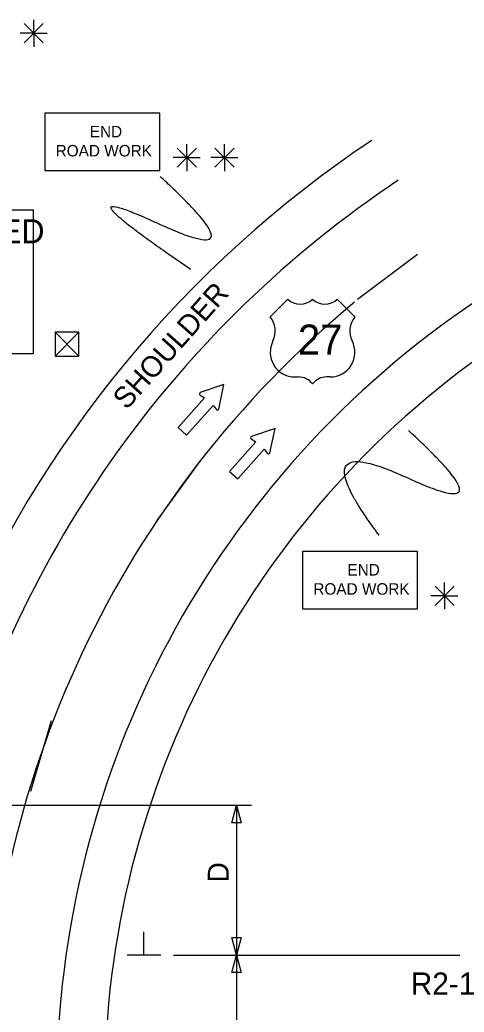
# Model space of a CAD drawing. Extents: x 16556 to 18479, y 5704 to 6974.
# Drawn here: x 17029.3 to 17177.7, y 6550.3 to 6881.5 of the extents above; entities that cross this region are included whole.
import ezdxf

# ---------------------------------------------------------------- set-up
doc = ezdxf.new("R2010")
doc.units = 0
for name, color, linetype in [('ALI_LEGAL_EX', 7, 'Continuous'), ('MT_SCRATCH_LEVEL_E', 7, 'Continuous'), ('PAVT_EDGE_EX', 7, 'Continuous'), ('TRAFFIC_SIGNS_PR', 7, 'Continuous'), ('TYPICAL_EX', 7, 'Continuous'), ('TYPICAL_TEXT_DIMEN_PR', 7, 'Continuous')]:
    doc.layers.add(name, color=color, linetype=linetype)

msp = doc.modelspace()

# ---------------------------------------------------------------- linework, layer by layer
at = {"layer": 'ALI_LEGAL_EX'}
msp.add_line((17039.84, 6647.53), (17032.85, 6623.88), dxfattribs=at)
for points in [[(17142.04, 6788.34), (17162.08, 6803.27)], [(17075.14, 6714.42), (17089.89, 6734.61)]]:
    msp.add_lwpolyline(points, dxfattribs=at)
msp.add_arc((17357.65, 6525.15), 340, 129.5666, 180, dxfattribs=at)
at = {"layer": 'MT_SCRATCH_LEVEL_E'}
for p, q in [((17097.48, 6759.79), (17089.6, 6757.11)), ((17095.77, 6751.62), (17097.48, 6759.79)), ((17091.04, 6755.33), (17082.24, 6745.42)), ((17089.5, 6756.28), (17091.04, 6755.33)), ((17085.03, 6742.93), (17093.84, 6752.84)), ((17093.84, 6752.84), (17094.96, 6751.43)), ((17082.24, 6745.42), (17085.03, 6742.93)), ((17114.56, 6745.13), (17106.68, 6742.45)), ((17112.85, 6736.96), (17114.56, 6745.13)), ((17108.12, 6740.67), (17099.32, 6730.76)), ((17106.59, 6741.62), (17108.12, 6740.67)), ((17102.12, 6728.28), (17110.92, 6738.19)), ((17110.92, 6738.19), (17112.04, 6736.77)), ((17099.32, 6730.76), (17102.12, 6728.28))]:
    msp.add_line(p, q, dxfattribs=at)
for centre, start, end in [((17089.75, 6756.67), 108.8028, 238.3418), ((17095.31, 6751.73), 218.4141, 348.1511), ((17106.84, 6742.01), 108.8028, 238.3418), ((17112.4, 6737.07), 218.4141, 348.1511)]:
    msp.add_arc(centre, 0.463, start, end, dxfattribs=at)
at = {"layer": 'PAVT_EDGE_EX'}
for radius, end in [(380, 157.5011), (364, 165.0045), (316, 180), (300, 180)]:
    msp.add_arc((17357.65, 6525.15), radius, 123.6935, end, dxfattribs=at)
at = {"layer": 'TRAFFIC_SIGNS_PR'}
for p, q in [((16995.55, 6818.12), (17033.95, 6818.12)), ((17033.95, 6770.12), (17033.95, 6818.12)), ((16995.55, 6770.12), (17033.95, 6770.12))]:
    msp.add_line(p, q, dxfattribs=at)
for points in [[(17037.68, 6831.2), (17076.08, 6831.2), (17076.08, 6850.4), (17037.68, 6850.4)], [(17123.73, 6684.89), (17162.13, 6684.89), (17162.13, 6704.09), (17123.73, 6704.09)]]:
    msp.add_lwpolyline(points, close=True, dxfattribs=at)
at = {"layer": 'TYPICAL_EX'}
for p, q in [((17112.93, 6782.38), (17118.83, 6788.28)), ((17141.23, 6782.38), (17135.33, 6788.28)), ((17121.17, 6762.32), (17122.35, 6762.32)), ((17132.98, 6762.32), (17131.8, 6762.32))]:
    msp.add_line(p, q, dxfattribs=at)
for centre, radius, start, end in [((17122.95, 6792.57), 5.96, 226.1404, 313.8596), ((17131.21, 6792.57), 5.96, 226.1404, 313.8596), ((17107.34, 6777.66), 7.31, 333.0977, 40.1936), ((17146.82, 6777.66), 7.31, 139.8064, 206.9023), ((17121.19, 6770.57), 8.24, 152.6698, 269.9013), ((17132.97, 6770.57), 8.24, 270.0987, 27.3302), ((17122.37, 6756.42), 5.91, 37.1038, 90.1385), ((17131.79, 6756.42), 5.91, 89.8615, 142.8962)]:
    msp.add_arc(centre, radius, start, end, dxfattribs=at)
at = {"layer": 'TYPICAL_TEXT_DIMEN_PR'}
for p, q in [((17033.98, 6877.09), (17033.98, 6881.55)), ((17030.79, 6880.28), (17037.17, 6873.9)), ((17037.17, 6880.28), (17030.79, 6873.9)), ((17033.98, 6877.09), (17029.44, 6877.09)), ((17033.98, 6877.09), (17037.17, 6877.09)), ((17033.98, 6877.09), (17038.46, 6877.09)), ((17033.98, 6877.09), (17033.98, 6872.59)), ((17081.92, 6838.76), (17088.29, 6832.38)), ((17088.29, 6838.76), (17081.92, 6832.38)), ((17085.1, 6835.57), (17085.1, 6840.03)), ((17094.47, 6838.76), (17100.85, 6832.38)), ((17100.85, 6838.76), (17094.47, 6832.38)), ((17097.66, 6835.57), (17097.66, 6840.03)), ((17085.1, 6835.57), (17080.57, 6835.57)), ((17085.1, 6835.57), (17088.29, 6835.57)), ((17085.1, 6835.57), (17089.58, 6835.57)), ((17085.1, 6835.57), (17085.1, 6831.07)), ((17097.66, 6835.57), (17093.13, 6835.57)), ((17097.66, 6835.57), (17100.85, 6835.57)), ((17097.66, 6835.57), (17102.14, 6835.57)), ((17097.66, 6835.57), (17097.66, 6831.07)), ((17041.08, 6777.24), (17049.08, 6769.24)), ((17041.08, 6769.24), (17049.08, 6777.24)), ((17167.97, 6692.45), (17174.34, 6686.07)), ((17174.34, 6692.45), (17167.97, 6686.07)), ((17171.16, 6689.26), (17171.16, 6693.72)), ((17171.16, 6689.26), (17166.62, 6689.26)), ((17171.16, 6689.26), (17174.34, 6689.26)), ((17171.16, 6689.26), (17175.63, 6689.26)), ((17171.16, 6689.26), (17171.16, 6684.76)), ((17012.72, 6619.33), (17106.65, 6619.33)), ((17100.08, 6613.47), (17101.65, 6619.33)), ((17101.65, 6619.33), (17101.65, 6569.33)), ((17101.65, 6619.33), (17103.22, 6613.47)), ((17101.65, 6613.47), (17100.08, 6613.47)), ((17103.22, 6613.47), (17101.65, 6613.47)), ((17070.77, 6569.33), (17070.77, 6577.11)), ((17101.65, 6569.33), (17100.08, 6575.19)), ((17100.08, 6575.19), (17101.65, 6575.19)), ((17101.65, 6575.19), (17103.22, 6575.19)), ((17103.22, 6575.19), (17101.65, 6569.33)), ((17076.4, 6569.33), (17065.15, 6569.33)), ((17080.65, 6569.33), (17176.22, 6569.33)), ((17100.08, 6563.47), (17101.65, 6569.33)), ((17101.65, 6569.33), (17101.65, 6519.33)), ((17101.65, 6569.33), (17103.22, 6563.47)), ((17101.65, 6563.47), (17100.08, 6563.47)), ((17103.22, 6563.47), (17101.65, 6563.47))]:
    msp.add_line(p, q, dxfattribs=at)
msp.add_lwpolyline([(17041.08, 6777.24), (17041.08, 6769.24), (17049.08, 6769.24), (17049.08, 6777.24)], close=True, dxfattribs=at)
for points in [[(17086.35, 6798.24), (17039.53, 6830.07), (17110.85, 6797.33), (17076.24, 6829.21)], [(17149.31, 6709.45), (17122.41, 6745.3), (17193.74, 6712.56), (17159.13, 6744.44)]]:
    msp.add_open_spline(points, degree=2, dxfattribs=at)

# ---------------------------------------------------------------- texts
at = {"layer": 'TRAFFIC_SIGNS_PR'}
for s, height, p in [('END', 3.831, (17052.68, 6842.32)), ('ROAD WORK', 3.831, (17041.29, 6835.94)), ('SPEED', 8, (17001.31, 6806.98)), ('END', 3.831, (17138.73, 6696.02)), ('ROAD WORK', 3.831, (17127.34, 6689.63)), ('R2-1', 7.44, (17159.87, 6556.06))]:
    msp.add_text(s, height=height, dxfattribs=at).set_placement(p)
at = {"layer": 'TYPICAL_EX'}
msp.add_text('27', height=10, dxfattribs=at).set_placement((17122.19, 6769.81))
at = {"layer": 'TYPICAL_TEXT_DIMEN_PR'}
for s, rotation, p in [('SHOULDER', 48.378, (17065, 6751.09)), ('D', 90, (17099.09, 6593.55))]:
    msp.add_text(s, height=7, rotation=rotation, dxfattribs=at).set_placement(p)

doc.saveas('drawing.dxf')
